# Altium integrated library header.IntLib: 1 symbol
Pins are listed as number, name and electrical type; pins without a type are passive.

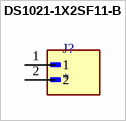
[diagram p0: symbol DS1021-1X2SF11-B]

## DS1021-1X2SF11-B
designator J?
2 position 2.54mm single row vertical pin header; MF: Connfly; MP: DS1021-1X2SF11-B
footprint CONNFLY_DS1021-1X2SF11-B
pins: 1, 2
